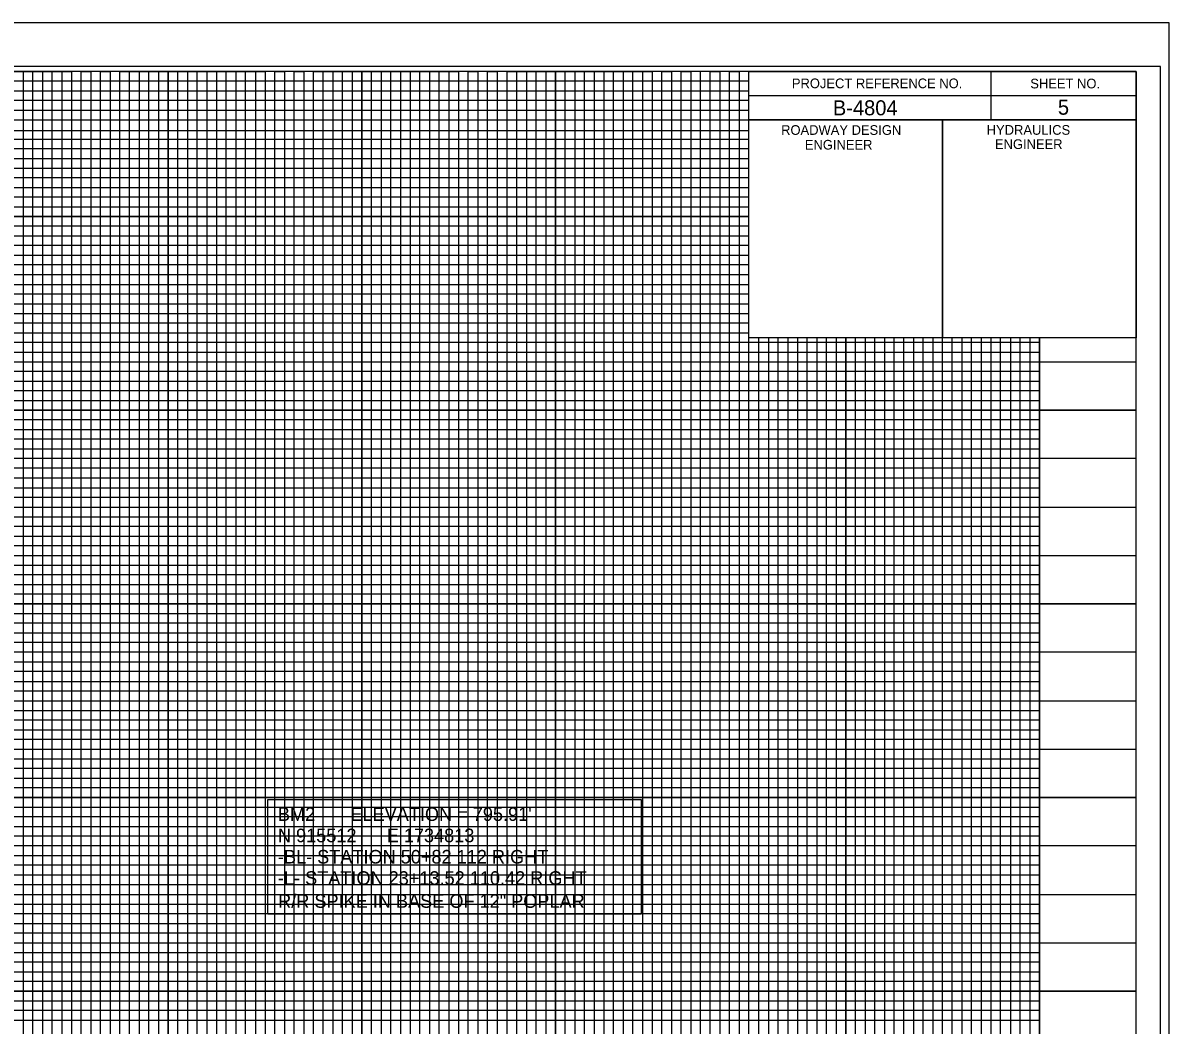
# Model space of a CAD drawing. Extents: x 573566 to 575250, y -53414 to -52314.
# Drawn here: x 574658 to 575250, y -52832 to -52314 of the extents above; entities that cross this region are included whole.
import ezdxf

# ---------------------------------------------------------------- set-up
doc = ezdxf.new("R2010")
doc.units = 0
for name, color, linetype in [('Prop Grid Mask', 7, 'Continuous'), ('Prop VPI Label', 7, 'Continuous'), ('Sheet Cutting Line CELL', 7, 'Continuous'), ('Sheet Data Field CELL', 7, 'Continuous'), ('Sheet DOT Grid CELL', 7, 'Continuous'), ('Sheet Layout Profile Border', 7, 'Continuous'), ('Sheet Plot Border Inside CELL', 7, 'Continuous'), ('Sheet Plot Border Outside CELL', 7, 'Continuous'), ('Sheet Profile CELL', 7, 'Continuous'), ('Sheet Profile Grid Major CELL', 7, 'Continuous'), ('Sheet Profile Grid Middle CELL', 7, 'Continuous'), ('Sheet Profile Grid Minor CELL', 7, 'Continuous')]:
    doc.layers.add(name, color=color, linetype=linetype)

msp = doc.modelspace()

# ---------------------------------------------------------------- linework, layer by layer
at = {"layer": 'Prop Grid Mask'}
msp.add_lwpolyline([(574784.83, -52714.99), (574977.56, -52714.99), (574977.56, -52774.25), (574784.83, -52774.25)], close=True, dxfattribs=at)
at = {"layer": 'Sheet Cutting Line CELL'}
msp.add_line((575250.31, -52314.05), (573566.31, -52314.05), dxfattribs=at)
at = {"layer": 'Sheet DOT Grid CELL'}
for p, q in [((574683.31, -52339.05), (574683.31, -53364.05)), ((574733.31, -52339.05), (574733.31, -53364.05)), ((574783.31, -52339.05), (574783.31, -53364.05)), ((574833.31, -52339.05), (574833.31, -53364.05)), ((574883.31, -52339.05), (574883.31, -53364.05)), ((574933.31, -52339.05), (574933.31, -53364.05)), ((574983.31, -52339.05), (574983.31, -53364.05)), ((573733.31, -52364.05), (575033.26, -52364.05)), ((573733.31, -52414.05), (575033.26, -52414.05)), ((573733.31, -52464.05), (575033.26, -52464.05)), ((575033.31, -53364.05), (575033.31, -52476.6)), ((575083.31, -53364.05), (575083.31, -52476.6)), ((575133.31, -53364.05), (575133.31, -52476.6)), ((575183.31, -53364.05), (575183.31, -52476.6)), ((573733.31, -52514.05), (575233.31, -52514.05)), ((573733.31, -52564.05), (575233.31, -52564.05)), ((573733.31, -52614.05), (575233.31, -52614.05)), ((573733.31, -52664.05), (575233.31, -52664.05)), ((573733.31, -52714.05), (575233.31, -52714.05)), ((573733.31, -52764.05), (575233.31, -52764.05)), ((573733.31, -52814.05), (575233.31, -52814.05))]:
    msp.add_line(p, q, dxfattribs=at)
at = {"layer": 'Sheet Layout Profile Border'}
msp.add_lwpolyline([(573783.31, -52339.05), (573783.31, -53364.05), (575183.31, -53364.05), (575183.31, -52476.6), (575033.26, -52476.6), (575033.26, -52339.05)], close=True, dxfattribs=at)
at = {"layer": 'Sheet Plot Border Inside CELL'}
msp.add_lwpolyline([(575245.81, -52336.5), (573579.31, -52336.5), (573579.31, -53391.6), (575245.81, -53391.6)], close=True, dxfattribs=at)
at = {"layer": 'Sheet Plot Border Outside CELL'}
msp.add_lwpolyline([(575250.31, -52314.05), (573566.31, -52314.05), (573566.31, -53414.05), (575250.31, -53414.05)], close=True, dxfattribs=at)
at = {"layer": 'Sheet Profile CELL'}
for p, q in [((575158.31, -52339.1), (575158.31, -52364.1)), ((575033.26, -52351.6), (575233.31, -52351.6)), ((575133.31, -52364.1), (575133.31, -52476.55))]:
    msp.add_line(p, q, dxfattribs=at)
for points in [[(575233.31, -52339.05), (573733.31, -52339.05), (573733.31, -53389.05), (575233.31, -53389.05)], [(575033.26, -52339.05), (575233.31, -52339.05), (575233.31, -52364.1), (575033.26, -52364.1)], [(575033.26, -52364.1), (575133.31, -52364.1), (575133.31, -52476.6), (575033.26, -52476.6)], [(575133.31, -52364.1), (575233.31, -52364.1), (575233.31, -52476.6), (575133.31, -52476.6)]]:
    msp.add_lwpolyline(points, close=True, dxfattribs=at)
at = {"layer": 'Sheet Profile Grid Major CELL'}
for points in [[(574633.31, -52339.05), (574683.31, -52339.05), (574683.31, -53364.05), (574733.31, -53364.05), (574733.31, -52339.05), (574783.31, -52339.05), (574783.31, -53364.05), (574833.31, -53364.05), (574833.31, -52339.05), (574883.31, -52339.05), (574883.31, -53364.05), (574933.31, -53364.05), (574933.31, -52339.05), (574983.31, -52339.05), (574983.31, -53364.05), (575033.31, -53364.05), (575033.31, -52339.05), (575059.61, -52339.05)], [(575033.26, -52414.05), (573733.41, -52414.05), (573733.41, -52364.1), (575033.26, -52364.1)], [(575233.31, -52514.05), (573733.31, -52514.05), (573733.31, -52464.05), (575033.26, -52464.05)], [(575083.31, -52476.6), (575083.31, -53364.05), (575133.31, -53364.05), (575133.31, -52476.6)], [(575183.31, -52476.6), (575183.31, -53364.05), (575233.31, -53364.05)], [(575233.31, -52614.05), (573733.31, -52614.05), (573733.31, -52564.05), (575233.31, -52564.05)], [(575233.31, -52714.05), (573733.31, -52714.05), (573733.31, -52664.05), (575233.31, -52664.05)], [(575233.31, -52814.05), (573733.31, -52814.05), (573733.31, -52764.05), (575233.31, -52764.05)]]:
    msp.add_lwpolyline(points, dxfattribs=at)
at = {"layer": 'Sheet Profile Grid Middle CELL'}
for points in [[(574608.31, -52339.05), (574658.31, -52339.05), (574658.31, -53364.05), (574708.31, -53364.05), (574708.31, -52339.05), (574758.31, -52339.05), (574758.31, -53364.05), (574808.31, -53364.05), (574808.31, -52339.05), (574858.31, -52339.05), (574858.31, -53364.05), (574908.31, -53364.05), (574908.31, -52339.05), (574958.31, -52339.05), (574958.31, -53364.05), (575008.31, -53364.05), (575008.31, -52339.05)], [(573733.31, -52389.05), (575033.26, -52389.05)], [(575033.26, -52439.05), (573733.31, -52439.05), (573733.31, -52489.1), (575233.31, -52489.1)], [(575058.31, -52476.6), (575058.31, -53364.05), (575108.31, -53364.05), (575108.31, -52476.6)], [(575158.31, -52476.6), (575158.31, -53364.05)], [(575233.31, -52539.05), (573733.31, -52539.05), (573733.31, -52589.05), (575233.31, -52589.05)], [(575233.31, -52639.05), (573733.31, -52639.05), (573733.31, -52689.05), (575233.31, -52689.05)], [(575233.31, -52739.05), (573733.31, -52739.05), (573733.31, -52789.05), (575233.31, -52789.05)]]:
    msp.add_lwpolyline(points, dxfattribs=at)
at = {"layer": 'Sheet Profile Grid Minor CELL'}
for p, q in [((575183.31, -52519.05), (573783.31, -52519.05)), ((573783.31, -52524.05), (575183.31, -52524.05)), ((575183.31, -52544.05), (573783.31, -52544.05))]:
    msp.add_line(p, q, dxfattribs=at)
for points in [[(574663.31, -53364.05), (574663.31, -52339.05), (574668.31, -52339.05), (574668.31, -53364.05)], [(574673.31, -53364.05), (574673.31, -52339.05), (574678.31, -52339.05), (574678.31, -53364.05)], [(574688.31, -53364.05), (574688.31, -52339.05), (574693.31, -52339.05), (574693.31, -53364.05)], [(574698.31, -53364.05), (574698.31, -52339.05), (574703.31, -52339.05), (574703.31, -53364.05)], [(574713.31, -53364.05), (574713.31, -52339.05), (574718.31, -52339.05), (574718.31, -53364.05)], [(574723.31, -53364.05), (574723.31, -52339.05), (574728.31, -52339.05), (574728.31, -53364.05)], [(574738.31, -53364.05), (574738.31, -52339.05), (574743.31, -52339.05), (574743.31, -53364.05)], [(574748.31, -53364.05), (574748.31, -52339.05), (574753.31, -52339.05), (574753.31, -53364.05)], [(574763.31, -53364.05), (574763.31, -52339.05), (574768.31, -52339.05), (574768.31, -53364.05)], [(574773.31, -53364.05), (574773.31, -52339.05), (574778.31, -52339.05), (574778.31, -53364.05)], [(574788.31, -53364.05), (574788.31, -52339.05), (574793.31, -52339.05), (574793.31, -53364.05)], [(574798.31, -53364.05), (574798.31, -52339.05), (574803.31, -52339.05), (574803.31, -53364.05)], [(574813.31, -53364.05), (574813.31, -52339.05), (574818.31, -52339.05), (574818.31, -53364.05)], [(574823.31, -53364.05), (574823.31, -52339.05), (574828.31, -52339.05), (574828.31, -53364.05)], [(574838.31, -53364.05), (574838.31, -52339.05), (574843.31, -52339.05), (574843.31, -53364.05)], [(574848.31, -53364.05), (574848.31, -52339.05), (574853.31, -52339.05), (574853.31, -53364.05)], [(574863.31, -53364.05), (574863.31, -52339.05), (574868.31, -52339.05), (574868.31, -53364.05)], [(574873.31, -53364.05), (574873.31, -52339.05), (574878.31, -52339.05), (574878.31, -53364.05)], [(574888.31, -53364.05), (574888.31, -52339.05), (574893.31, -52339.05), (574893.31, -53364.05)], [(574898.31, -53364.05), (574898.31, -52339.05), (574903.31, -52339.05), (574903.31, -53364.05)], [(574913.31, -53364.05), (574913.31, -52339.05), (574918.31, -52339.05), (574918.31, -53364.05)], [(574923.31, -53364.05), (574923.31, -52339.05), (574928.31, -52339.05), (574928.31, -53364.05)], [(574938.31, -53364.05), (574938.31, -52339.05), (574943.31, -52339.05), (574943.31, -53364.05)], [(574948.31, -53364.05), (574948.31, -52339.05), (574953.31, -52339.05), (574953.31, -53364.05)], [(574963.31, -53364.05), (574963.31, -52339.05), (574968.31, -52339.05), (574968.31, -53364.05)], [(574973.31, -53364.05), (574973.31, -52339.05), (574978.31, -52339.05), (574978.31, -53364.05)], [(574988.31, -53364.05), (574988.31, -52339.05), (574993.31, -52339.05), (574993.31, -53364.05)], [(574998.31, -53364.05), (574998.31, -52339.05), (575003.31, -52339.05), (575003.31, -53364.05)], [(575013.31, -53364.05), (575013.31, -52339.05), (575018.31, -52339.05), (575018.31, -53364.05)], [(575023.31, -53364.05), (575023.31, -52339.05), (575028.31, -52339.05), (575028.31, -53364.05)], [(575033.26, -52344.05), (573783.31, -52344.05), (573783.31, -52349.05), (575033.26, -52349.05)], [(575033.26, -52354.05), (573783.31, -52354.05), (573783.31, -52359.05), (575033.26, -52359.05)], [(575033.26, -52369.8), (573784.31, -52369.8), (573784.31, -52374.05), (575033.26, -52374.05)], [(575033.26, -52379.05), (573783.31, -52379.05), (573783.31, -52384.05), (575033.26, -52384.05)], [(575033.26, -52394.05), (573783.31, -52394.05), (573783.31, -52399.05), (575033.26, -52399.05)], [(575033.26, -52404.05), (573783.31, -52404.05), (573783.31, -52409.05), (575033.26, -52409.05)], [(575033.26, -52419.05), (573783.31, -52419.05), (573783.31, -52424.05), (575033.26, -52424.05)], [(575033.26, -52429.05), (573783.31, -52429.05), (573783.31, -52434.05), (575033.26, -52434.05)], [(575033.26, -52444.05), (573783.31, -52444.05), (573783.31, -52449.05), (575033.26, -52449.05)], [(575033.26, -52454.05), (573783.31, -52454.05), (573783.31, -52459.05), (575033.26, -52459.05)], [(575033.26, -52469.05), (573783.31, -52469.05), (573783.31, -52474.05), (575033.26, -52474.05)], [(575183.31, -52479.05), (573783.31, -52479.05), (573783.31, -52479.05), (573783.31, -52499.05), (575183.31, -52499.05)], [(575038.31, -53364.05), (575038.31, -52476.6)], [(575043.31, -52476.6), (575043.31, -53364.05), (575048.31, -53364.05), (575048.31, -52476.6)], [(575053.31, -52476.6), (575053.31, -53364.05), (575063.31, -53364.05), (575063.31, -52476.6)], [(575068.31, -52476.6), (575068.31, -53364.05), (575073.31, -53364.05), (575073.31, -52476.6)], [(575078.31, -52476.6), (575078.31, -53364.05), (575088.31, -53364.05), (575088.31, -52476.6)], [(575093.31, -52476.6), (575093.31, -53364.05), (575098.31, -53364.05), (575098.31, -52476.6)], [(575103.31, -52476.6), (575103.31, -53364.05), (575113.31, -53364.05), (575113.31, -52476.6)], [(575118.31, -52476.6), (575118.31, -53364.05)], [(575118.31, -53364.05), (575123.31, -53364.05), (575123.31, -52476.6)], [(575128.31, -52476.6), (575128.31, -53364.05), (575138.31, -53364.05), (575138.31, -52476.6)], [(575143.31, -52476.6), (575143.31, -53364.05), (575148.31, -53364.05), (575148.31, -52476.6)], [(575153.31, -52476.6), (575153.31, -53364.05), (575163.31, -53364.05), (575163.31, -52476.6)], [(575168.31, -52476.6), (575168.31, -53364.05), (575173.31, -53364.05), (575173.31, -52476.6)], [(575178.31, -52476.6), (575178.31, -53364.05), (575188.31, -53364.05)], [(573783.31, -52484.05), (575183.31, -52484.05)], [(575183.31, -52494.05), (573783.31, -52494.05)], [(575183.31, -52504.05), (573783.31, -52504.05), (573783.31, -52509.05), (575183.31, -52509.05)], [(575183.31, -52529.05), (573783.31, -52529.05), (573783.31, -52534.05), (575183.31, -52534.05)], [(575183.31, -52549.05), (573783.31, -52549.05), (573783.31, -52554.05), (575183.31, -52554.05)], [(575183.31, -52559.05), (573783.31, -52559.05)], [(573783.31, -52569.05), (575183.31, -52569.05)], [(575183.31, -52574.05), (573783.31, -52574.05), (573783.31, -52579.05), (575183.31, -52579.05)], [(575183.31, -52584.05), (573783.31, -52584.05), (573783.31, -52594.05), (575183.31, -52594.05)], [(575183.31, -52599.05), (573783.31, -52599.05), (573783.31, -52604.05), (575183.31, -52604.05)], [(575183.31, -52609.05), (573783.31, -52609.05), (573783.31, -52619.05), (575183.31, -52619.05)], [(575183.31, -52624.05), (573783.31, -52624.05), (573783.31, -52629.05), (575183.31, -52629.05)], [(575183.31, -52634.05), (573783.31, -52634.05), (573783.31, -52644.05), (575183.31, -52644.05)], [(575183.31, -52649.05), (573783.31, -52649.05), (573783.31, -52654.05), (575183.31, -52654.05)], [(575183.31, -52659.05), (573783.31, -52659.05), (573783.31, -52669.05), (575183.31, -52669.05)], [(575183.31, -52674.05), (573783.31, -52674.05), (573783.31, -52679.05), (575183.31, -52679.05)], [(575183.31, -52684.05), (573783.31, -52684.05), (573783.31, -52694.05), (575183.31, -52694.05)], [(575183.31, -52699.05), (573783.31, -52699.05), (573783.31, -52704.05), (575183.31, -52704.05)], [(575183.31, -52709.05), (573783.31, -52709.05), (573783.31, -52719.05), (575183.31, -52719.05)], [(575183.31, -52724.05), (573783.31, -52724.05), (573783.31, -52729.05), (575183.31, -52729.05)], [(575183.31, -52734.05), (573783.31, -52734.05), (573783.31, -52744.05), (575183.31, -52744.05)], [(575183.31, -52749.05), (573783.31, -52749.05), (573783.31, -52754.05), (575183.31, -52754.05)], [(575183.31, -52759.05), (573783.31, -52759.05), (573783.31, -52769.05), (575183.31, -52769.05)], [(575183.31, -52774.05), (573783.31, -52774.05), (573783.31, -52779.05), (575183.31, -52779.05)], [(575183.31, -52784.05), (573783.31, -52784.05), (573783.31, -52794.05), (575183.31, -52794.05)], [(575183.31, -52799.05), (573783.31, -52799.05), (573783.31, -52804.05), (575183.31, -52804.05)], [(575183.31, -52809.05), (573783.31, -52809.05), (573783.31, -52819.05), (575183.31, -52819.05)], [(575183.31, -52824.05), (573783.31, -52824.05), (573783.31, -52829.05), (575183.31, -52829.05)]]:
    msp.add_lwpolyline(points, dxfattribs=at)

# ---------------------------------------------------------------- texts
at = {"layer": 'Prop VPI Label'}
for s, p in [("BM2       ELEVATION = 795.91'", (574789.97, -52726.12)), ('N 915512      E 1734813', (574789.97, -52737.12)), ('-BL- STATION 50+82 112 RIGHT', (574789.97, -52748.12)), ('-L- STATION 23+13.52 110.42 RIGHT', (574789.97, -52759.12)), ('R/R SPIKE IN BASE OF 12" POPLAR', (574790.1, -52771))]:
    msp.add_text(s, height=7, rotation=360, dxfattribs=at).set_placement(p)
at = {"layer": 'Sheet Data Field CELL'}
for s, p in [('B-4804', (575076.64, -52361.75)), ('5', (575192.87, -52361.45))]:
    msp.add_text(s, height=7.75, dxfattribs=at).set_placement(p)
at = {"layer": 'Sheet Profile CELL'}
for s, height, p in [('PROJECT REFERENCE NO.', 5.0001, (575055.46, -52347.75)), ('SHEET NO.', 5, (575178.61, -52347.85)), ('ROADWAY DESIGN', 5.0001, (575049.91, -52371.85)), ('HYDRAULICS', 5, (575156.11, -52371.8)), ('ENGINEER', 5, (575062.16, -52379.45)), ('ENGINEER', 5, (575160.36, -52379.15))]:
    msp.add_text(s, height=height, dxfattribs=at).set_placement(p)

doc.saveas('drawing.dxf')
